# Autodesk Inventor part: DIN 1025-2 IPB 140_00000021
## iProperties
Created: 2006-02
Part Number: DIN 1025-2 IPB 140_00000021
Material: Default
Document SubType Name: Modeling
Designer: 40664
Manufacturer: Standard
Standards Organization: Custom
Stock Number: DIN 1025-2 IPB 140
Mass: 27320 g
Surface Area: 51344.8 cm^2
Volume: 27320 cm^3
Density: 1 g/cm^3
G_L: 6500.000 mm
G_W: 140.000 mm
G_H: 140.000 mm
AFG_Item: IPB 140
CSToolsMass: 27.0
CSToolsVolume: 27319967.0
CSToolsArea: 51345.0
Author: 40664
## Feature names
1. AFG_Detailed_DIN 1025-2 IPB 140_00000021 [Extrusion]
2. AFG_Simplified_DIN 1025-2 IPB 140_00000021 [Extrusion]
